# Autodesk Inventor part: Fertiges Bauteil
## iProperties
Created: 2011-05
Part Number: Fertiges Bauteil
Document SubType Name: Modeling
Designer: Lorenz Humpel
Density: 1 g/cm^3
Author: Lorenz Humpel
